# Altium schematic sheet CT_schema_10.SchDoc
size 147 x 119 mm
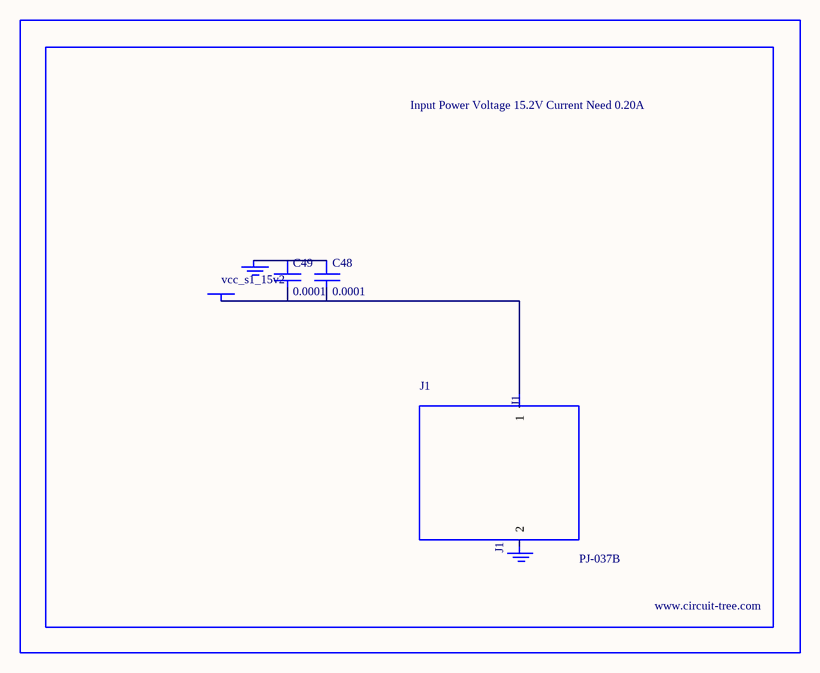
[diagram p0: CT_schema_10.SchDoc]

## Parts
BORDER9  (no value)
C48  0.0001  [EXV-9H]
C49  0.0001  [EXV-9H]
GND_INSTANCE_9_0  (no value)
GND_INSTANCE_9_1  (no value)
J1  PJ-037B  [PJ-037B_PACKAGE]
POWER_INSTANCE_9_0  vcc_s1_15v2

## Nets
NetC48_1: C48.1 C49.1 GND_INSTANCE_9_0.0(GND)
NetC48_2: C48.2 C49.2 J1.1 POWER_INSTANCE_9_0.0(PWR)

Not connected (* = marked no-connect by the designer): GND_INSTANCE_9_1 0(GND); J1 2

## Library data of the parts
BORDER9 = BORDER_PAGE9
C48 C49 = EDK107M035A9HAA
GND_INSTANCE_9_0 GND_INSTANCE_9_1 = GND
POWER_INSTANCE_9_0 = PWR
